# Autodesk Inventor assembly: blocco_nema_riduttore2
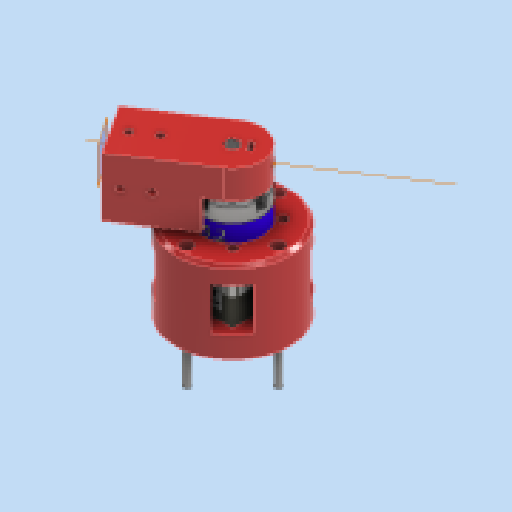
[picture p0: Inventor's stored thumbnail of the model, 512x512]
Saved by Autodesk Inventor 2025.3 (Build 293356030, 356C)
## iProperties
Created: 2026-01
Part Number: blocco_nema_riduttore2
Document SubType Name: Assembly
Designer: R5800u
Author: R5800u
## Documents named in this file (6)
- C:\Users\R5800u\Desktop\antropomorfo_nema2\blocco_nema_riduttore2.iam
- C:\Users\R5800u\Desktop\antropomorfo_nema2\NEMA 42SHDC3030Z.ipt
- C:\Users\R5800u\Desktop\antropomorfo_nema2\blocco_albero.ipt
- C:\Users\R5800u\Desktop\antropomorfo_nema2\blocco_nema.ipt
- C:\Users\R5800u\Desktop\antropomorfo_nema2\ANSI B18.3.1M - M4x0,7 x 50(1).ipt
- C:\Users\R5800u\Desktop\antropomorfo_nema2\riduttore_nema17.ipt
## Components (8 placed, 5 different names)
1. NEMA 42SHDC3030Z:1 — Angolo:3, Coincidente:15, Coincidente:16, Angolo:4
2. blocco_nema:1 — Angolo:2, Tangente:1, Allineato:1, Coincidente:10, Coincidente:12, Coincidente:14, Rotazionale:1
3. Vite forgiata a testa incassata - Metrico M4x0,7 x 50:2 — Coincidente:10
4. Vite forgiata a testa incassata - Metrico M4x0,7 x 50:1 — Coincidente:12
5. Vite forgiata a testa incassata - Metrico M4x0,7 x 50:4 — Coincidente:14
6. Vite forgiata a testa incassata - Metrico M4x0,7 x 50:3 — Rotazionale:1
7. blocco_albero:1 — Rotazionale:2
8. riduttore_nema17:1 — Coincidente:15, Coincidente:16, Angolo:4, Rotazionale:2
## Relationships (12: Mate 5, Angle 3, RevoluteJoint 2, Tangent 1, Flush 1)
- Angolo:2 [Angle]: blocco_nema:1
- Angolo:3 [Angle]: NEMA 42SHDC3030Z:1
- Tangente:1: blocco_nema:1
- Allineato:1 [Flush]: blocco_nema:1
- Coincidente:10 [Mate]: blocco_nema:1 ↔ Vite forgiata a testa incassata - Metrico M4x0,7 x 50:2
- Coincidente:12 [Mate]: blocco_nema:1 ↔ Vite forgiata a testa incassata - Metrico M4x0,7 x 50:1
- Coincidente:14 [Mate]: blocco_nema:1 ↔ Vite forgiata a testa incassata - Metrico M4x0,7 x 50:4
- Rotazionale:1 [RevoluteJoint]: blocco_nema:1 ↔ Vite forgiata a testa incassata - Metrico M4x0,7 x 50:3
- Coincidente:15 [Mate]: NEMA 42SHDC3030Z:1 ↔ riduttore_nema17:1
- Coincidente:16 [Mate]: NEMA 42SHDC3030Z:1 ↔ riduttore_nema17:1
- Angolo:4 [Angle]: NEMA 42SHDC3030Z:1 ↔ riduttore_nema17:1
- Rotazionale:2 [RevoluteJoint]: blocco_albero:1 ↔ riduttore_nema17:1
